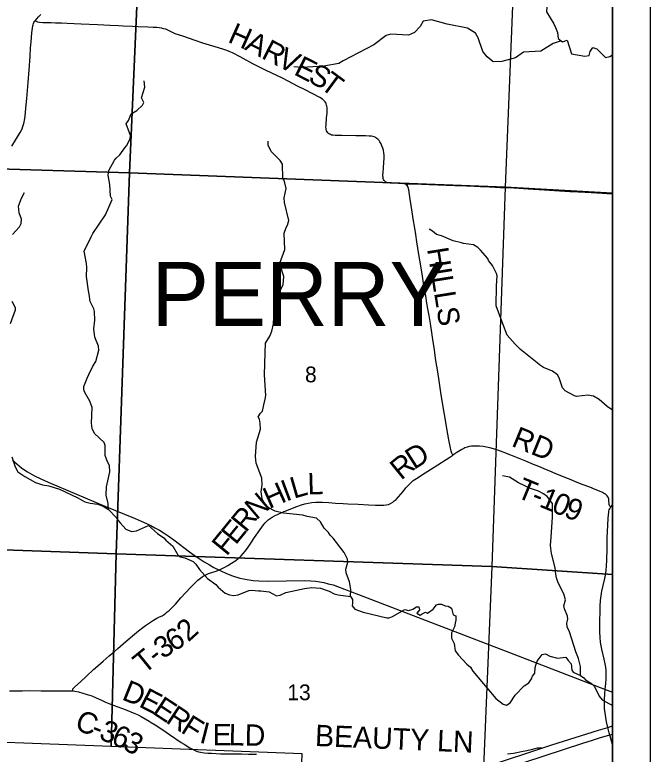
# Model space of a CAD drawing. Extents: x 0 to 34, y 0 to 22.
# Drawn here: x 7.308 to 9, y 17.712 to 19.68 of the extents above; entities that cross this region are included whole.
import ezdxf

# ---------------------------------------------------------------- set-up
doc = ezdxf.new("R2010")
doc.units = 0
for name, color, linetype in [('GM_X_County_Road', 7, 'Continuous'), ('GM_X_County_Road_Text', 7, 'Continuous'), ('GM_X_Interchange_Ramps', 7, 'Continuous'), ('GM_X_Interstate_Route', 7, 'Continuous'), ('GM_X_Minor_River', 7, 'Continuous'), ('GM_X_Rail_Line', 7, 'Continuous'), ('GM_X_Section', 7, 'Continuous'), ('GM_X_Section_Text', 7, 'Continuous'), ('GM_X_Township_Road', 7, 'Continuous'), ('GM_X_Township_Road_Text', 7, 'Continuous'), ('GM_X_Township_Text', 7, 'Continuous'), ('GM_X_Unincorporated_Text', 7, 'Continuous'), ('SH_Data', 7, 'Continuous')]:
    doc.layers.add(name, color=color, linetype=linetype)

msp = doc.modelspace()

# ---------------------------------------------------------------- linework, layer by layer
at = {"layer": 'GM_X_County_Road'}
for points in [[(7.362, 19.6636), (7.3626, 19.6643), (7.3666, 19.6692), (7.3715, 19.6746), (7.3776, 19.6805)], [(7.3005, 19.3305), (7.3103, 19.3464), (7.3226, 19.3671), (7.3276, 19.3767), (7.33, 19.3831), (7.3317, 19.3883), (7.3333, 19.3947), (7.3343, 19.4), (7.3358, 19.4096), (7.3379, 19.4315), (7.34, 19.457), (7.3436, 19.4995), (7.3466, 19.5338), (7.3489, 19.5691), (7.3504, 19.5924), (7.3514, 19.6078), (7.3535, 19.6325), (7.3549, 19.6448), (7.356, 19.6508), (7.3568, 19.6537), (7.3579, 19.6565), (7.3593, 19.6592), (7.3608, 19.6618), (7.362, 19.6636)], [(8.9, 17.7384), (8.8963, 17.751), (8.8925, 17.7639), (8.8911, 17.7689), (8.887, 17.7839), (8.8838, 17.7983), (8.8818, 17.8099), (8.8799, 17.8229), (8.8787, 17.8339), (8.8784, 17.8422), (8.8782, 17.8484), (8.8783, 17.8576), (8.8791, 17.873), (8.8802, 17.8854), (8.8818, 17.9008), (8.8826, 17.9131), (8.8828, 17.9254), (8.8824, 17.9346), (8.8814, 17.9438), (8.88, 17.9529), (8.8776, 17.965), (8.8709, 17.992), (8.869, 18.0011), (8.8678, 18.0104), (8.8667, 18.0227), (8.8659, 18.0382), (8.8657, 18.0537), (8.8659, 18.0722), (8.8663, 18.0877), (8.8669, 18.1064), (8.8677, 18.1219), (8.869, 18.1343), (8.8711, 18.1466), (8.8746, 18.1618), (8.8792, 18.1798), (8.881, 18.1889), (8.8825, 18.2012), (8.8834, 18.2135), (8.8841, 18.229), (8.8851, 18.2598), (8.8854, 18.2722), (8.8858, 18.2878), (8.8871, 18.3219), (8.8884, 18.3405), (8.8897, 18.3561), (8.8902, 18.3592), (8.891, 18.3623), (8.8921, 18.3653), (8.8936, 18.3681), (8.8948, 18.37)], [(8.8948, 18.37), (8.8953, 18.3708), (8.8992, 18.3758), (8.9, 18.3766)], [(7.294, 17.8814), (7.3009, 17.8813), (7.3112, 17.8813), (7.3288, 17.8815), (7.3473, 17.8816), (7.3787, 17.8813), (7.4373, 17.8815), (7.456, 17.8815), (7.4621, 17.8811)], [(7.4621, 17.8811), (7.4628, 17.881), (7.4684, 17.8802), (7.4776, 17.8782), (7.4895, 17.8751), (7.5013, 17.8715), (7.513, 17.8674), (7.5246, 17.8628), (7.5387, 17.8563), (7.5499, 17.8511), (7.5585, 17.8476), (7.573, 17.8422), (7.6019, 17.831), (7.6279, 17.8207), (7.6365, 17.817), (7.6448, 17.8129), (7.6557, 17.8068), (7.6662, 17.8003), (7.6714, 17.7971), (7.6818, 17.7906), (7.7024, 17.7769), (7.7204, 17.7648), (7.7511, 17.7439), (7.759, 17.7389), (7.7744, 17.7296), (7.7847, 17.7242), (7.7916, 17.7209), (7.797, 17.7189), (7.8026, 17.7176), (7.8125, 17.7164), (7.8225, 17.7156), (7.8318, 17.7149), (7.8558, 17.7136), (7.865, 17.7133), (7.8867, 17.7132), (7.9115, 17.7131), (7.9301, 17.7128), (7.9518, 17.7123)]]:
    msp.add_lwpolyline(points, dxfattribs=at)
at = {"layer": 'GM_X_Interchange_Ramps'}
msp.add_lwpolyline([(8.711, 17.7284), (8.7023, 17.7287), (8.6994, 17.7283), (8.6927, 17.7266), (8.6833, 17.7244), (8.6715, 17.7217), (8.6613, 17.7194), (8.6531, 17.7177), (8.6445, 17.7161), (8.6362, 17.7146), (8.62, 17.7122)], dxfattribs=at)
at = {"layer": 'GM_X_Interstate_Route'}
for points in [[(8.4432, 17.6401), (8.711, 17.7284), (8.7383, 17.7374), (8.8004, 17.7573), (8.8627, 17.7766), (8.887, 17.7839), (8.9, 17.7877)], [(8.6143, 17.6743), (8.8209, 17.742), (8.8464, 17.75)], [(8.8464, 17.75), (8.8654, 17.7559), (8.8925, 17.7639), (8.9, 17.7662)]]:
    msp.add_lwpolyline(points, dxfattribs=at)
at = {"layer": 'GM_X_Minor_River'}
for points in [[(8.6806, 19.744), (8.6936, 19.7338), (8.7038, 19.7343), (8.7156, 19.7298), (8.7255, 19.715), (8.7241, 19.6877), (8.7433, 19.656), (8.7475, 19.6461), (8.7532, 19.6329), (8.7548, 19.6174), (8.7666, 19.6083), (8.7787, 19.6126), (8.7903, 19.5762), (8.826, 19.57), (8.8373, 19.5716), (8.8403, 19.5826), (8.8474, 19.5929), (8.8577, 19.5895), (8.8805, 19.5665), (8.8927, 19.5688), (8.9, 19.5734)], [(8.7632, 19.611), (8.7417, 19.604), (8.7088, 19.583), (8.6626, 19.5804), (8.6415, 19.5651), (8.6051, 19.5558), (8.582, 19.5549), (8.5657, 19.5685), (8.5546, 19.5828), (8.5419, 19.6192), (8.5346, 19.6309), (8.5137, 19.6448), (8.4591, 19.6547), (8.4173, 19.667), (8.3954, 19.6635), (8.3875, 19.6486), (8.3728, 19.6326), (8.3562, 19.6257), (8.3092, 19.6281), (8.2967, 19.625), (8.2638, 19.6001), (8.1822, 19.5576), (8.1705, 19.5507), (8.1308, 19.5432), (8.0725, 19.5399), (8.0508, 19.5416)], [(7.558, 18.363), (7.557, 18.3798), (7.5512, 18.4018), (7.5526, 18.4242), (7.5611, 18.4637), (7.5599, 18.4804), (7.5549, 18.4906), (7.5484, 18.5073), (7.549, 18.5339), (7.546, 18.5422), (7.5201, 18.566), (7.5144, 18.5792), (7.5121, 18.5933), (7.5141, 18.635), (7.5084, 18.6521), (7.4935, 18.6763), (7.4916, 18.6827), (7.4919, 18.6911), (7.5009, 18.7132), (7.5057, 18.7227), (7.5162, 18.7451), (7.5237, 18.7573), (7.5315, 18.7873), (7.5307, 18.7983), (7.5215, 18.8218), (7.5184, 18.8442), (7.5209, 18.8678), (7.5204, 18.8901), (7.5185, 18.8977), (7.5089, 18.9167), (7.5058, 18.9368), (7.5046, 18.9459), (7.4988, 18.9834), (7.5002, 19.0073), (7.4994, 19.0183), (7.4928, 19.0509), (7.5119, 19.0894), (7.516, 19.0977), (7.5498, 19.148), (7.567, 19.1884), (7.5632, 19.1978), (7.5611, 19.2282), (7.5568, 19.2536), (7.5587, 19.2654), (7.5733, 19.2928), (7.5778, 19.2989), (7.5876, 19.3077), (7.6015, 19.3263), (7.606, 19.3313), (7.6157, 19.3503), (7.6161, 19.3587), (7.6046, 19.3897), (7.6113, 19.3985), (7.6181, 19.4164), (7.6335, 19.4252), (7.6482, 19.4397), (7.652, 19.4469), (7.6451, 19.459), (7.654, 19.4879), (7.6524, 19.5039)], [(8.2021, 18.1317), (8.2028, 18.1503), (8.1996, 18.1715), (8.1907, 18.1954), (8.1899, 18.2045), (8.1947, 18.2239), (8.1939, 18.2311), (8.1851, 18.2488), (8.1557, 18.2877), (8.1477, 18.2956), (8.1434, 18.3021), (8.1316, 18.3141), (8.1224, 18.3311), (8.1118, 18.3405), (8.0863, 18.3453), (8.0753, 18.3483), (8.0234, 18.3536), (8.0014, 18.3596), (7.9828, 18.3689), (7.9759, 18.3757), (7.9694, 18.3863), (7.9667, 18.3924), (7.9643, 18.4106), (7.9669, 18.4295), (7.9656, 18.4466), (7.9509, 18.4867), (7.9493, 18.5049), (7.9513, 18.5432), (7.9621, 18.5771), (7.9612, 18.593), (7.9593, 18.604), (7.9562, 18.61), (7.9622, 18.6199), (7.9674, 18.6249), (7.9715, 18.6424), (7.9748, 18.6572), (7.977, 18.6674), (7.9732, 18.722), (7.9747, 18.7808), (7.9761, 18.8062), (7.987, 18.8249), (7.9925, 18.8382), (7.9966, 18.8576), (7.999, 18.891), (8.0123, 18.9411), (8.0228, 18.9613), (8.0249, 18.9837), (8.0153, 19.0109), (8.0137, 19.0193), (8.0275, 19.0558), (8.0257, 19.099), (8.0305, 19.1142), (8.0346, 19.1199), (8.0379, 19.1328), (8.0263, 19.1806), (8.0258, 19.1927), (8.0309, 19.2178), (8.0255, 19.2401), (8.0217, 19.245), (8.021, 19.2826), (8.0145, 19.2924), (7.9909, 19.3161), (7.9832, 19.3335), (7.9827, 19.3438)], [(7.3019, 19.0951), (7.3105, 19.105), (7.3203, 19.1161), (7.3248, 19.1248), (7.3259, 19.1358), (7.3201, 19.1533), (7.3182, 19.1707), (7.3256, 19.1924), (7.3339, 19.2076)], [(8.9, 18.6282), (8.8851, 18.6378), (8.8638, 18.6559), (8.8486, 18.6649), (8.8342, 18.6675), (8.8039, 18.6646), (8.7986, 18.6661), (8.7739, 18.6796), (8.7662, 18.6875), (8.7577, 18.7144), (8.7535, 18.722), (8.7394, 18.7314), (8.7159, 18.7415), (8.7048, 18.749), (8.6991, 18.7535), (8.655, 18.7893), (8.6401, 18.8036), (8.6191, 18.8273), (8.6075, 18.8576), (8.5898, 18.9057), (8.5906, 18.9592), (8.5927, 18.985), (8.5907, 18.9914), (8.58, 19.0126), (8.5697, 19.0258), (8.5674, 19.0315), (8.5479, 19.0537), (8.5407, 19.0605), (8.5292, 19.0676), (8.5027, 19.0716), (8.4978, 19.0731), (8.475, 19.0787), (8.4446, 19.0918), (8.4313, 19.0951), (8.4203, 19.1045), (8.4115, 19.1098)], [(7.297, 18.859), (7.3097, 18.8947), (7.3097, 18.9), (7.3016, 18.9167)], [(7.2999, 18.5037), (7.3091, 18.4776), (7.3167, 18.4639), (7.3346, 18.4511), (7.363, 18.4357), (7.382, 18.429), (7.3986, 18.4264), (7.4274, 18.4175)], [(8.8141, 17.922), (8.8143, 17.9455), (8.8093, 17.9671), (8.8016, 17.9849), (8.7849, 18.0379), (8.7792, 18.0511), (8.7783, 18.061), (8.7805, 18.0716), (8.7797, 18.0796), (8.7716, 18.0993), (8.7701, 18.1076), (8.7741, 18.1232), (8.7699, 18.1391), (8.7545, 18.1686), (8.7506, 18.1818), (8.7491, 18.1913), (8.7467, 18.2087), (8.7373, 18.2462), (8.7345, 18.2678), (8.7359, 18.2898), (8.7397, 18.3433), (8.7402, 18.3794), (8.7253, 18.3986), (8.7158, 18.4054), (8.7025, 18.4125), (8.6809, 18.4196), (8.6497, 18.4346), (8.6254, 18.4496), (8.6068, 18.4533)], [(7.4274, 18.4175), (7.476, 18.3949), (7.4946, 18.3844), (7.5086, 18.3803), (7.5294, 18.3774), (7.5434, 18.3721), (7.5575, 18.3635), (7.578, 18.3423), (7.5829, 18.3352), (7.589, 18.328), (7.6035, 18.3117), (7.619, 18.305), (7.6326, 18.307), (7.6643, 18.3208)], [(7.6643, 18.3208), (7.6878, 18.2996), (7.7049, 18.2883), (7.7099, 18.2823), (7.7286, 18.2661), (7.7427, 18.2434), (7.7484, 18.2381), (7.761, 18.2352), (7.7834, 18.2251), (7.7906, 18.2179), (7.8002, 18.2036), (7.8212, 18.1798), (7.8436, 18.164), (7.8501, 18.1565), (7.868, 18.1414), (7.8794, 18.1365), (7.8915, 18.1351), (7.9033, 18.1367), (7.9316, 18.1482), (7.9396, 18.1491), (7.957, 18.1476), (7.963, 18.1473), (7.9854, 18.1444), (8.0048, 18.1343), (8.0143, 18.1359), (8.0297, 18.1428), (8.0793, 18.1533), (8.0993, 18.1561), (8.1225, 18.1544), (8.1456, 18.1466), (8.1589, 18.139), (8.1695, 18.1361), (8.2021, 18.1317), (8.2075, 18.1242), (8.2076, 18.1147), (8.2061, 18.1075), (8.2134, 18.098), (8.2361, 18.0902), (8.2984, 18.0754), (8.3048, 18.0755), (8.3135, 18.0786), (8.3471, 18.0977), (8.3566, 18.0948), (8.3683, 18.0986), (8.3781, 18.1044), (8.3841, 18.1044), (8.3853, 18.0965), (8.3789, 18.0877), (8.3877, 18.0828), (8.393, 18.0863), (8.402, 18.0901), (8.407, 18.0875), (8.4217, 18.0982), (8.4311, 18.1097), (8.436, 18.1116), (8.4443, 18.1113), (8.4538, 18.1071), (8.4618, 18.106), (8.4705, 18.1008), (8.4756, 18.083), (8.4828, 18.0804), (8.4825, 18.0694), (8.481, 18.061), (8.4792, 18.0515), (8.4706, 18.0356), (8.471, 18.0215), (8.478, 18.0068), (8.4811, 17.9871), (8.4892, 17.9757), (8.5117, 17.9516), (8.5216, 17.9437), (8.5277, 17.9335), (8.5892, 17.8611), (8.6082, 17.846), (8.6177, 17.843), (8.6267, 17.8492), (8.6406, 17.8697), (8.6647, 17.8941), (8.6764, 17.9026), (8.6843, 17.9129), (8.6865, 17.9197), (8.6925, 17.9277), (8.6939, 17.9429), (8.6954, 17.9493), (8.6991, 17.96), (8.7119, 17.9779), (8.7209, 17.9791), (8.7331, 17.9731), (8.7532, 17.9679), (8.7752, 17.9703), (8.7817, 17.9616), (8.7897, 17.9533), (8.7917, 17.9359), (8.7951, 17.9306), (8.8141, 17.922), (8.8229, 17.9156), (8.8274, 17.91), (8.8434, 17.9006), (8.8518, 17.893), (8.8637, 17.8666), (8.8725, 17.8571)], [(8.8725, 17.8571), (8.8999, 17.8421), (8.9, 17.8421)]]:
    msp.add_lwpolyline(points, dxfattribs=at)
at = {"layer": 'GM_X_Rail_Line'}
for points in [[(6.4764, 15.22), (8.4272, 15.1429), (8.9, 15.1329), (8.9, 20.2439), (7.9141, 20.2806), (7.3096, 20.3035), (6.6357, 20.3306)], [(7.3019, 18.4949), (7.3137, 18.4848), (7.3271, 18.474), (7.3422, 18.4639), (7.3602, 18.4535), (7.3773, 18.445), (7.3974, 18.4363), (7.5481, 18.3729), (7.6285, 18.3394), (7.6445, 18.3326), (7.6585, 18.3263), (7.6701, 18.3206), (7.6808, 18.3151), (7.6938, 18.3082), (7.7032, 18.3021), (7.7169, 18.2931), (7.7313, 18.2829), (7.7732, 18.2512), (7.7859, 18.2421), (7.8126, 18.2246), (7.8267, 18.2161), (7.8385, 18.2097), (7.8551, 18.2013), (7.8721, 18.1934), (7.8879, 18.1873), (7.9076, 18.1813), (7.9265, 18.1774), (7.9425, 18.175), (7.9583, 18.1738), (7.9806, 18.1733), (8.0806, 18.1743), (8.0961, 18.1738), (8.1089, 18.1726), (8.1201, 18.171), (8.1306, 18.1691), (8.1429, 18.1662), (8.1559, 18.1628), (8.1676, 18.1588), (8.2236, 18.1376), (8.66, 17.9701), (8.8785, 17.8858), (8.9, 17.8778)]]:
    msp.add_lwpolyline(points, dxfattribs=at)
at = {"layer": 'GM_X_Section'}
for points in [[(6.6348, 20.3279), (7.6587, 20.2884), (7.6132, 19.2594), (6.5918, 19.2905)], [(7.6587, 20.2884), (8.6557, 20.2521), (8.6142, 19.2215), (7.6132, 19.2594)], [(6.5918, 19.2905), (7.6132, 19.2594), (7.5782, 18.246), (6.5595, 18.2824)], [(7.6132, 19.2594), (8.6142, 19.2215), (8.5787, 18.2117), (7.5782, 18.246)], [(6.5595, 18.2824), (7.5782, 18.246), (7.5651, 17.7332), (6.5395, 17.7719)], [(7.5782, 18.246), (8.5787, 18.2117), (8.5361, 17.186), (8.0548, 17.2024), (8.0736, 17.7137), (7.5651, 17.7332)]]:
    msp.add_lwpolyline(points, close=True, dxfattribs=at)
at = {"layer": 'GM_X_Township_Road'}
for points in [[(8.3515, 19.227), (8.3508, 19.2277), (8.3482, 19.2294), (8.3453, 19.2304), (8.3422, 19.2309), (8.3391, 19.2312), (8.3298, 19.2313), (8.308, 19.2322), (8.3018, 19.233), (8.2989, 19.2338), (8.2961, 19.2351), (8.2937, 19.2369), (8.2916, 19.2392), (8.2902, 19.2419), (8.2892, 19.2448), (8.2886, 19.2479), (8.2884, 19.251), (8.2883, 19.2541), (8.2886, 19.2603), (8.2898, 19.2727), (8.2911, 19.2882), (8.2916, 19.2975), (8.2914, 19.3068), (8.2907, 19.313), (8.2895, 19.3196), (8.2877, 19.3256), (8.2857, 19.3318), (8.2833, 19.3371), (8.2802, 19.3424), (8.2781, 19.3452), (8.2764, 19.3474), (8.2745, 19.3493), (8.2723, 19.3512), (8.2697, 19.3529), (8.2676, 19.3541), (8.2647, 19.3555), (8.2611, 19.3564), (8.2575, 19.3569), (8.2518, 19.3574), (8.242, 19.3579), (8.2159, 19.3581), (8.1789, 19.359), (8.1609, 19.359), (8.1547, 19.3594), (8.1517, 19.3601), (8.1488, 19.3611), (8.146, 19.3625), (8.1435, 19.3643), (8.1413, 19.3664), (8.1395, 19.369), (8.1381, 19.3717), (8.1373, 19.3747), (8.1368, 19.3777), (8.1366, 19.3808), (8.137, 19.3875), (8.1385, 19.4055), (8.1396, 19.4179), (8.1399, 19.4281), (8.1396, 19.4336), (8.139, 19.4368), (8.1383, 19.4397), (8.1371, 19.4432), (8.1359, 19.4454), (8.1344, 19.4482), (8.1327, 19.4504), (8.1303, 19.453), (8.1274, 19.4556), (8.1205, 19.4602), (8.0816, 19.4801), (8.0613, 19.4905), (8.0227, 19.5102), (7.9761, 19.5331), (7.9424, 19.5498), (7.9083, 19.568), (7.8882, 19.5785), (7.8793, 19.5822), (7.8731, 19.5847), (7.8624, 19.5884), (7.8415, 19.5946), (7.827, 19.5991), (7.809, 19.605), (7.7883, 19.6116), (7.7552, 19.6228), (7.7356, 19.6294), (7.7196, 19.6376), (7.7106, 19.6414), (7.7046, 19.6431), (7.6986, 19.6445), (7.6925, 19.6456), (7.6863, 19.6462), (7.677, 19.6466), (7.662, 19.6471), (7.6367, 19.648), (7.6212, 19.6489), (7.5964, 19.65), (7.584, 19.6505), (7.5623, 19.6516), (7.5282, 19.6532), (7.4849, 19.6553), (7.4663, 19.6561), (7.4477, 19.6567), (7.4322, 19.6574), (7.4167, 19.6581), (7.4043, 19.6586), (7.3828, 19.6591), (7.3736, 19.6597), (7.3694, 19.6606), (7.3656, 19.6621), (7.362, 19.6636)], [(8.3515, 19.227), (8.3531, 19.2283), (8.3548, 19.2294), (8.3567, 19.2301), (8.3603, 19.2304), (8.3709, 19.2301), (8.4112, 19.2284), (8.4795, 19.2257), (8.5106, 19.2245), (8.5323, 19.2239), (8.5478, 19.2233), (8.5725, 19.2222), (8.5879, 19.2215), (8.6003, 19.2209), (8.619, 19.2202), (8.6376, 19.2193), (8.6747, 19.217), (8.7181, 19.2143), (8.7583, 19.2117), (8.7862, 19.2101), (8.7986, 19.2095), (8.8079, 19.2092), (8.8265, 19.2084), (8.8575, 19.2062), (8.9, 19.2034)], [(8.4741, 18.5082), (8.4715, 18.5135), (8.4701, 18.5188), (8.4674, 18.5309), (8.4639, 18.5492), (8.4611, 18.5645), (8.4519, 18.6165), (8.447, 18.6471), (8.4427, 18.6747), (8.4382, 18.7056), (8.4343, 18.73), (8.432, 18.7448), (8.4294, 18.7599), (8.4248, 18.7944), (8.4224, 18.8097), (8.4186, 18.8343), (8.4147, 18.8587), (8.4111, 18.8802), (8.4081, 18.8974), (8.4056, 18.9123), (8.4022, 18.9322), (8.3983, 18.9535), (8.3936, 18.9842), (8.3892, 19.0116), (8.3843, 19.042), (8.379, 19.0755), (8.3758, 19.0957), (8.3733, 19.1119), (8.3692, 19.1369), (8.3665, 19.1557), (8.3608, 19.1894), (8.3571, 19.214), (8.3557, 19.2201), (8.3546, 19.2229), (8.3529, 19.2255), (8.3515, 19.227)], [(8.8948, 18.37), (8.8928, 18.3722), (8.8912, 18.374), (8.8904, 18.3772), (8.8898, 18.3888), (8.8894, 18.3918), (8.8886, 18.3947), (8.8873, 18.3974), (8.8856, 18.3999), (8.8836, 18.4021), (8.8813, 18.404), (8.8787, 18.4057), (8.8733, 18.4085), (8.8648, 18.4123), (8.8533, 18.417), (8.8389, 18.4227), (8.8215, 18.4295), (8.8012, 18.4376), (8.7897, 18.4422), (8.7753, 18.448), (8.7467, 18.4598), (8.7323, 18.4658), (8.718, 18.4718), (8.7036, 18.4778), (8.6893, 18.4837), (8.6692, 18.4919), (8.6462, 18.501), (8.629, 18.5079), (8.6087, 18.516), (8.5913, 18.5225), (8.5824, 18.5253), (8.5734, 18.5276), (8.5643, 18.5295), (8.5551, 18.531), (8.5459, 18.5321), (8.5397, 18.5325), (8.5304, 18.5324), (8.5243, 18.5319), (8.5182, 18.531), (8.5122, 18.5295), (8.5064, 18.5274), (8.5035, 18.5262), (8.4981, 18.5234), (8.485, 18.515), (8.4741, 18.5082)], [(7.4621, 17.8811), (7.4623, 17.8826), (7.4626, 17.8845), (7.4631, 17.886), (7.4646, 17.888), (7.468, 17.8915), (7.4827, 17.9053), (7.4989, 17.9203), (7.5181, 17.9381), (7.5291, 17.9473), (7.5432, 17.9596), (7.5595, 17.9738), (7.5737, 17.9854), (7.5827, 17.9938), (7.5971, 18.006), (7.6104, 18.0173), (7.6271, 18.0322), (7.6371, 18.0407), (7.6488, 18.0495), (7.6563, 18.0549), (7.6691, 18.0636), (7.6771, 18.0691), (7.6865, 18.0745), (7.6933, 18.0776), (7.7007, 18.0809), (7.7063, 18.0845), (7.7101, 18.0874), (7.7141, 18.0909), (7.7188, 18.0952), (7.7357, 18.1119), (7.7502, 18.1283), (7.7756, 18.1558), (7.7886, 18.1689), (7.7953, 18.1752), (7.8025, 18.181), (7.8075, 18.1845), (7.8127, 18.1878), (7.8182, 18.1906), (7.8238, 18.1929), (7.8326, 18.1958), (7.8444, 18.1995), (7.8502, 18.2018), (7.8587, 18.2056), (7.867, 18.2098), (7.8751, 18.2144), (7.8856, 18.2211), (7.8966, 18.2282), (7.9032, 18.2336), (7.9106, 18.2401), (7.9166, 18.2463), (7.9222, 18.2534), (7.9291, 18.2634), (7.9366, 18.2739), (7.9462, 18.2888), (7.9611, 18.3101), (7.9705, 18.3231), (7.9745, 18.3279), (7.9787, 18.332), (7.9827, 18.3357), (7.9878, 18.3397), (7.9932, 18.3431), (8.0012, 18.3477), (8.009, 18.3515), (8.021, 18.3569), (8.0412, 18.3649), (8.0566, 18.3707), (8.0713, 18.3758), (8.0804, 18.3787), (8.0895, 18.3809), (8.0991, 18.3823), (8.1098, 18.3833), (8.1184, 18.3833), (8.1273, 18.3832), (8.1443, 18.382), (8.1621, 18.3805), (8.1825, 18.3794), (8.195, 18.3789), (8.2227, 18.3775), (8.2503, 18.376), (8.2688, 18.3752), (8.2843, 18.3751), (8.2911, 18.3753), (8.2974, 18.376), (8.3031, 18.3773), (8.3087, 18.3796), (8.3143, 18.3829), (8.3187, 18.3865), (8.3234, 18.3905), (8.3301, 18.3969), (8.3361, 18.404), (8.3423, 18.4119), (8.3496, 18.4212), (8.3563, 18.4287), (8.3626, 18.4347), (8.3692, 18.4405), (8.3774, 18.4465), (8.4011, 18.4614), (8.4247, 18.4764), (8.4666, 18.5031), (8.4741, 18.5082)]]:
    msp.add_lwpolyline(points, dxfattribs=at)
at = {"layer": 'GM_X_Unincorporated_Text'}
for points in [[(8.9, 19.2054), (8.9, 20.2441), (8.6557, 20.2521), (8.6142, 19.2215)], [(8.9, 18.1906), (8.9, 19.2054), (8.6142, 19.2215), (8.5787, 18.2117)], [(8.9, 17.1728), (8.9, 18.1906), (8.5787, 18.2117), (8.5361, 17.186)]]:
    msp.add_lwpolyline(points, close=True, dxfattribs=at)
at = {"layer": 'SH_Data'}
for p, q in [((9, 21), (9, 14)), ((8.9, 20.9), (8.9, 14.1))]:
    msp.add_line(p, q, dxfattribs=at)

# ---------------------------------------------------------------- texts
at = {"layer": 'GM_X_County_Road_Text'}
for s, rotation, p in [('D', 337.9848, (7.5905, 17.8588)), ('E', 332.6951, (7.6356, 17.8406)), ('E', 326.6499, (7.672, 17.8219)), ('C', 337.8362, (7.4647, 17.7803)), ('R', 326.3706, (7.7074, 17.7986)), ('F', 327.5745, (7.7474, 17.7721)), ('3', 337.7772, (7.5295, 17.7539)), ('6', 337.5647, (7.5619, 17.7407)), ('I', 345.7177, (7.7974, 17.7439)), ('E', 0.1494, (7.8352, 17.7362)), ('L', 358.7485, (7.8773, 17.7363)), ('D', 358.7524, (7.9198, 17.7354)), ('-', 337.8203, (7.5079, 17.7627)), ('3', 330.6179, (7.5926, 17.7281))]:
    msp.add_text(s, height=0.0568, rotation=rotation, dxfattribs=at).set_placement(p)
at = {"layer": 'GM_X_Section_Text'}
for s, height, p in [('8', 0.0419, (8.0809, 18.7021)), ('13', 0.04186, (8.0338, 17.8562))]:
    msp.add_text(s, height=height, rotation=0, dxfattribs=at).set_placement(p)
at = {"layer": 'GM_X_Township_Road_Text'}
for s, height, rotation, p in [('H', 0.0568, 335.8859, (7.8726, 19.6089)), ('A', 0.0568, 333.1743, (7.9175, 19.5888)), ('R', 0.0568, 333.0108, (7.9621, 19.5662)), ('V', 0.0568, 333.0182, (8.0037, 19.5451)), ('E', 0.0568, 333.0114, (8.0483, 19.5224)), ('S', 0.0568, 332.7996, (8.0861, 19.5031)), ('T', 0.0568, 323.587, (8.1181, 19.4869)), ('HILLS', 0.05682, 279.1103, (8.4056, 19.0571)), ('RD', 0.05682, 337.8313, (8.6279, 18.5334)), ('D', 0.0568, 32.7545, (8.3714, 18.4685)), ('R', 0.0568, 39.1944, (8.3366, 18.44)), ('L', 0.0568, 1.706, (8.0882, 18.4034)), ('I', 0.0568, 20.62, (8.0304, 18.3843)), ('L', 0.0568, 16.1779, (8.0511, 18.3921)), ('T', 0.0568, 337.5707, (8.6407, 18.3975)), ('H', 0.0568, 23.9869, (7.9855, 18.3643)), ('1', 0.0568, 337.6396, (8.7017, 18.3724)), ('N', 0.0568, 40.0845, (7.9509, 18.3343)), ('-', 0.0568, 337.5874, (8.68, 18.3813)), ('0', 0.0568, 337.8449, (8.7342, 18.359)), ('9', 0.0568, 338.5693, (8.7674, 18.3455)), ('R', 0.0568, 50.4978, (7.9231, 18.3002)), ('E', 0.0568, 50.7887, (7.8963, 18.2674)), ('F', 0.0568, 50.7888, (7.872, 18.2377)), ('2', 0.0568, 42.3062, (7.7702, 18.0092)), ('6', 0.0568, 31.2993, (7.7308, 17.9839)), ('3', 0.0568, 34.966, (7.7029, 17.9644)), ('T', 0.0568, 39.0955, (7.6524, 17.9238)), ('-', 0.0568, 38.1721, (7.6852, 17.9505)), ('BEAUTY LN', 0.05682, 357.563, (8.1067, 17.7344))]:
    msp.add_text(s, height=height, rotation=rotation, dxfattribs=at).set_placement(p)
at = {"layer": 'GM_X_Township_Text'}
msp.add_text('PERRY', height=0.17045, rotation=0, dxfattribs=at).set_placement((7.6727, 18.8522))

doc.saveas('drawing.dxf')
